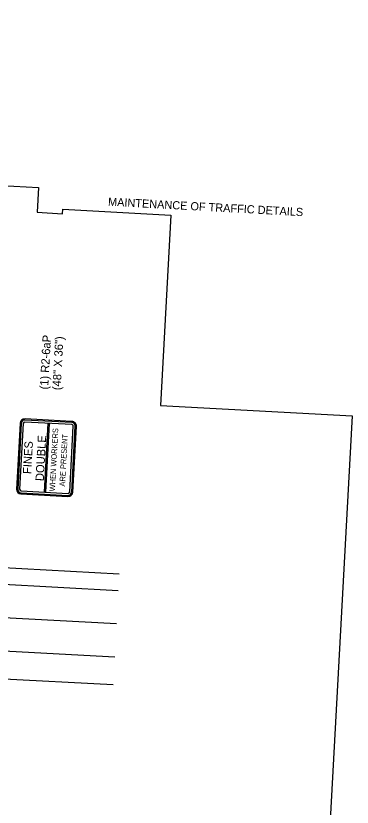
# Model space of a CAD drawing. Extents: x 879461 to 881100, y 1566470 to 1567598.
# Drawn here: x 880858 to 881100, y 1567029 to 1567598 of the extents above; entities that cross this region are included whole.
import ezdxf

# ---------------------------------------------------------------- set-up
doc = ezdxf.new("R2010")
doc.units = 0
for name, color, linetype in [('P_TC_Signs_Permanent', 7, 'Continuous'), ('R_Annotation', 7, 'Continuous'), ('R_Border', 7, 'Continuous'), ('R_Draft', 7, 'Continuous'), ('R_No Plot', 7, 'Continuous')]:
    doc.layers.add(name, color=color, linetype=linetype)

msp = doc.modelspace()

# ---------------------------------------------------------------- linework, layer by layer
at = {"layer": 'P_TC_Signs_Permanent'}
for p, q in [((880898.73, 1567305.57), (880865.03, 1567307.4)), ((880898.78, 1567306.41), (880865.08, 1567308.24)), ((880861.52, 1567305.06), (880858.96, 1567257.88)), ((880862.37, 1567305.01), (880859.8, 1567257.83)), ((880863.77, 1567304.93), (880861.2, 1567257.75)), ((880898.65, 1567304.16), (880864.95, 1567306)), ((880897.15, 1567255.8), (880899.72, 1567302.98)), ((880898.56, 1567255.72), (880901.12, 1567302.9)), ((880899.4, 1567255.68), (880901.96, 1567302.86)), ((880862.27, 1567256.57), (880895.97, 1567254.74)), ((880862.14, 1567254.32), (880895.84, 1567252.49)), ((880862.19, 1567255.16), (880895.89, 1567253.33))]:
    msp.add_line(p, q, dxfattribs=at)
for centre, radius, start, end in [((880864.89, 1567304.87), 3.37, 86.8871, 176.8871), ((880864.89, 1567304.87), 2.53, 86.8871, 176.8871), ((880898.59, 1567303.04), 3.37, 356.8871, 86.8871), ((880864.89, 1567304.87), 1.13, 86.8871, 176.8871), ((880898.59, 1567303.04), 1.12, 356.8871, 86.8871), ((880898.59, 1567303.04), 2.53, 356.8871, 86.8871), ((880862.33, 1567257.69), 3.37, 176.8871, 266.8871), ((880862.33, 1567257.69), 2.53, 176.8871, 266.8871), ((880862.33, 1567257.69), 1.12, 176.8871, 266.8871), ((880896.03, 1567255.86), 3.37, 266.8871, 356.8871), ((880896.03, 1567255.86), 2.53, 266.8871, 356.8871), ((880896.03, 1567255.86), 1.12, 266.8871, 356.8871)]:
    msp.add_arc(centre, radius, start, end, dxfattribs=at)
at = {"layer": 'R_Draft'}
for p, q in [((880879.12, 1567255.65), (880881.8, 1567305.08)), ((880882.51, 1567305.04), (880879.82, 1567255.61)), ((880881.8, 1567305.08), (880883.21, 1567305)), ((880881.8, 1567305.08), (880882.51, 1567305.04)), ((880879.82, 1567255.61), (880879.12, 1567255.65)), ((880932.7, 1567196.83), (880499.33, 1567220.4)), ((880932.05, 1567184.88), (880498.68, 1567208.45)), ((880930.75, 1567160.97), (880497.38, 1567184.54)), ((880929.45, 1567137.07), (880496.08, 1567160.64)), ((880928.37, 1567117.15), (880495, 1567140.72))]:
    msp.add_line(p, q, dxfattribs=at)
at = {"layer": 'R_No Plot'}
for points in [[(881099.91, 1567310.44), (881054.22, 1566470.26), (879461.22, 1566556.89), (879517.82, 1567597.67), (880700.13, 1567533.37), (880697.45, 1567484.05), (880874.78, 1567474.4), (880873.82, 1567456.58), (880891.99, 1567455.59), (880892.17, 1567458.84), (880969.72, 1567454.62)], [(880969.72, 1567454.62), (880962.29, 1567317.92), (881099.91, 1567310.44)]]:
    msp.add_lwpolyline(points, dxfattribs=at)

# ---------------------------------------------------------------- texts
at = {"layer": 'P_TC_Signs_Permanent'}
for s, height, p in [('WHEN WORKERS', 4, (880886.51, 1567256.07)), ('DOUBLE', 6, (880878.51, 1567263.43)), ('ARE PRESENT', 4, (880893.72, 1567259.62)), ('FINES', 6, (880869.49, 1567268.5))]:
    msp.add_text(s, height=height, rotation=86.8871, dxfattribs=at).set_placement(p)
at = {"layer": 'R_Annotation'}
for s, p in [('(1) R2-6aP', (880881.64, 1567329.21)), ('(48" X 36")', (880890.62, 1567328.72))]:
    msp.add_text(s, height=6, rotation=86.8871, dxfattribs=at).set_placement(p)
at = {"layer": 'R_Border'}
msp.add_text('MAINTENANCE OF TRAFFIC DETAILS', height=5.862, rotation=356.8871, dxfattribs=at).set_placement((880924.55, 1567461.38))

doc.saveas('drawing.dxf')
